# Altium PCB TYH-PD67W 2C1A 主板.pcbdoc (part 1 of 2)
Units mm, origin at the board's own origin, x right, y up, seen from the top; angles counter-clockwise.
Board outline 94.32 x 66.89 mm, 5 copper layers (Top Layer, Signal Layer 3, Signal Layer 1, Signal Layer 2, Bottom Layer), stack 0.941 mm thick; 52 components, 153 nets, 152 pads, 297 vias.
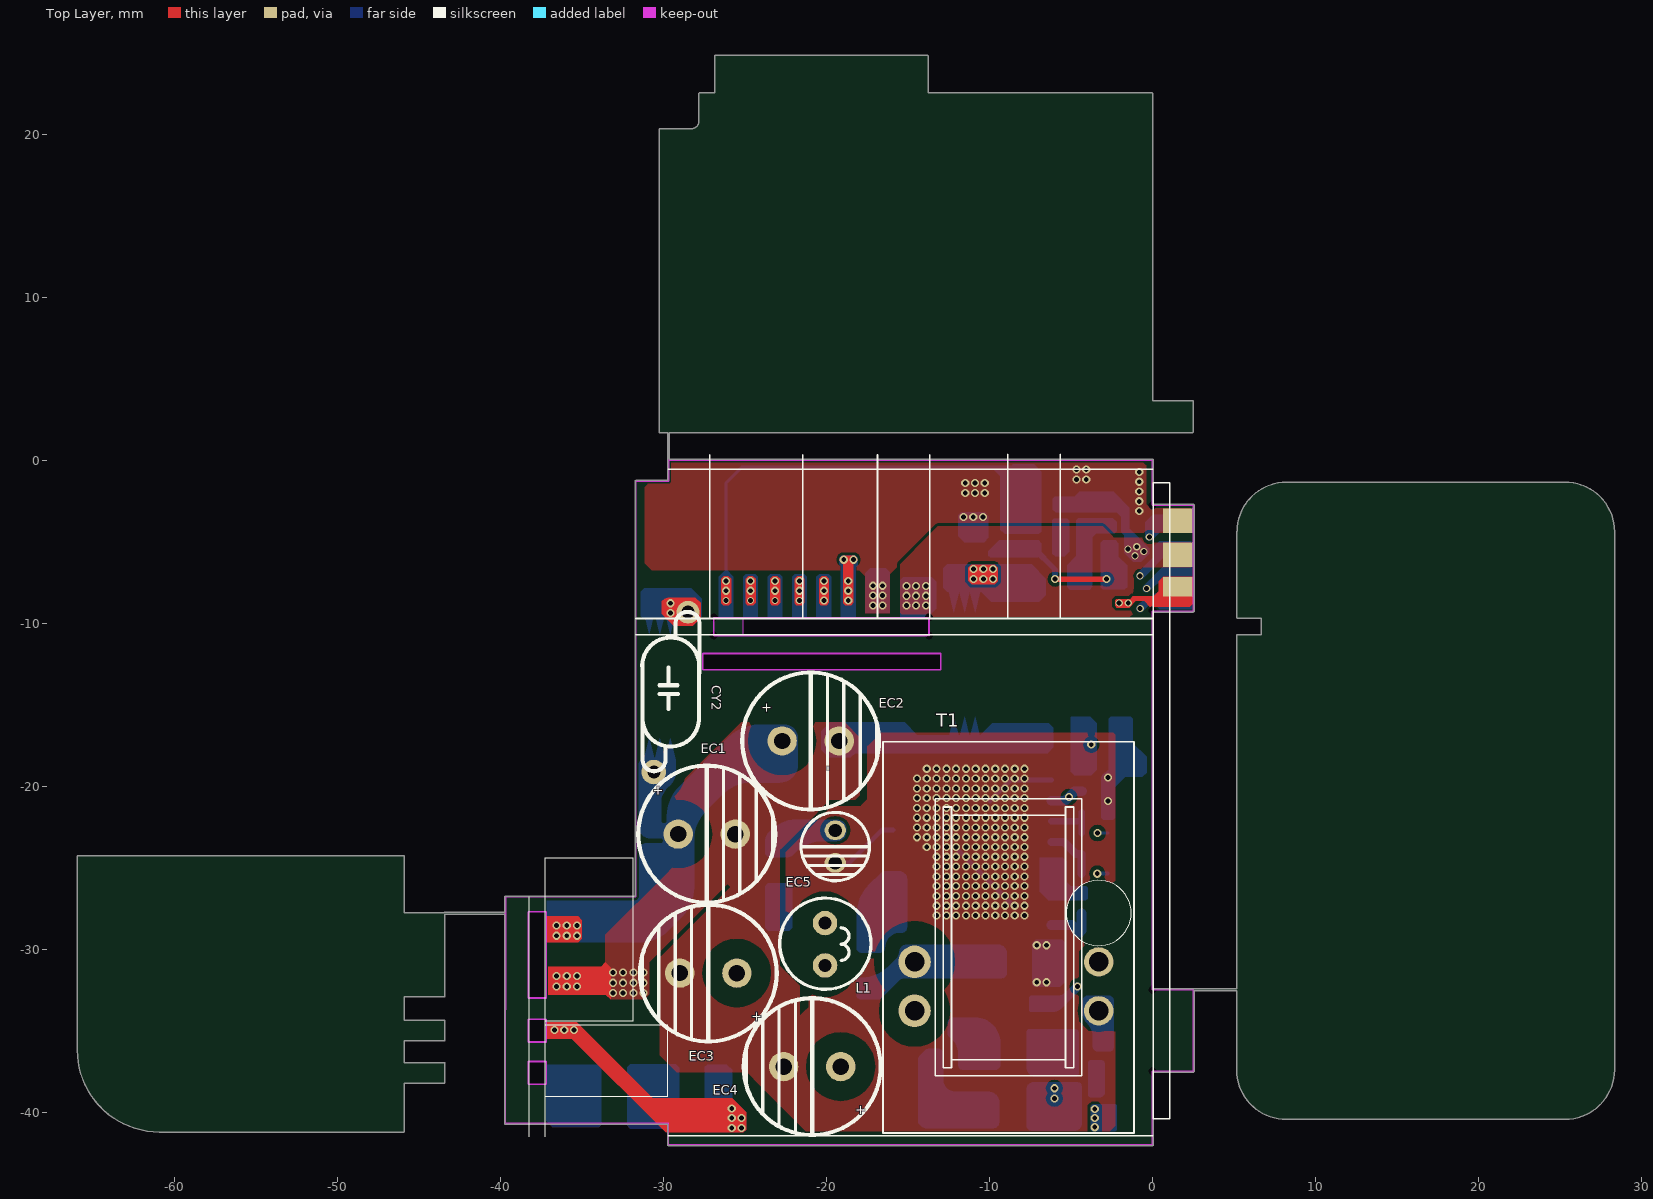
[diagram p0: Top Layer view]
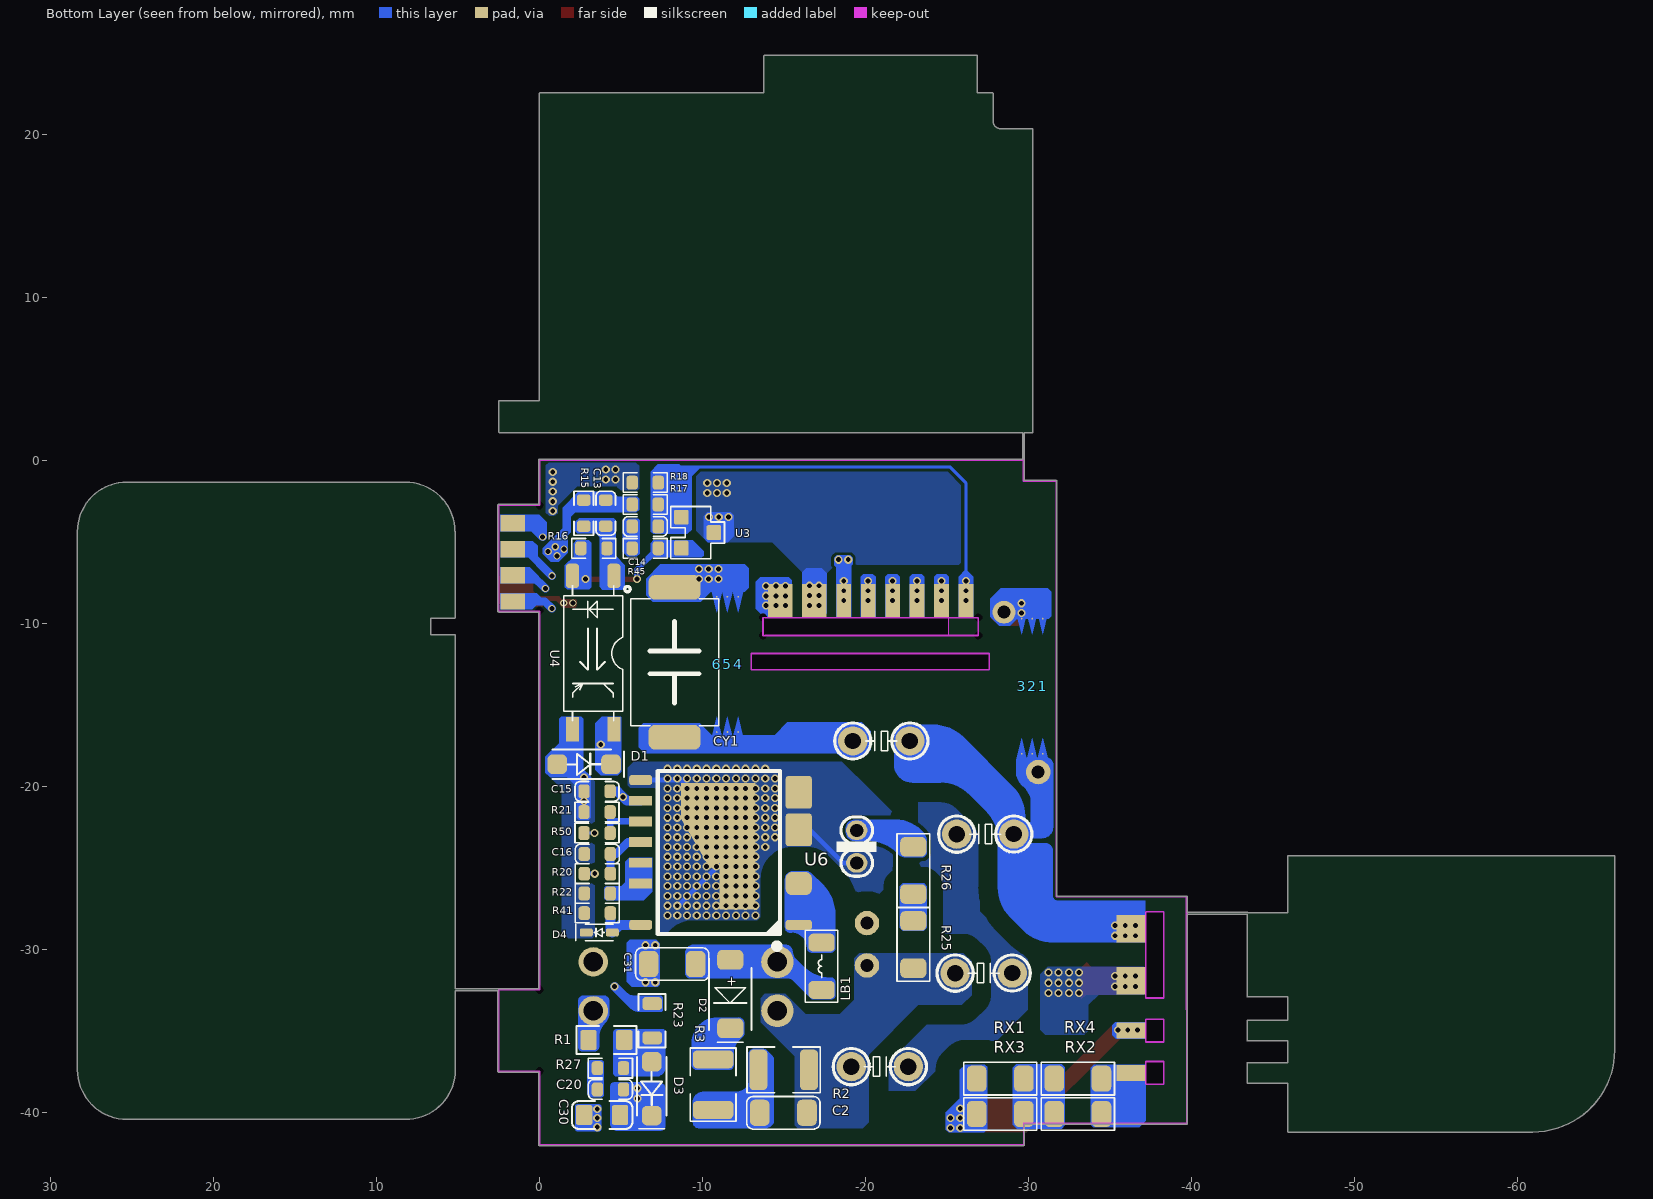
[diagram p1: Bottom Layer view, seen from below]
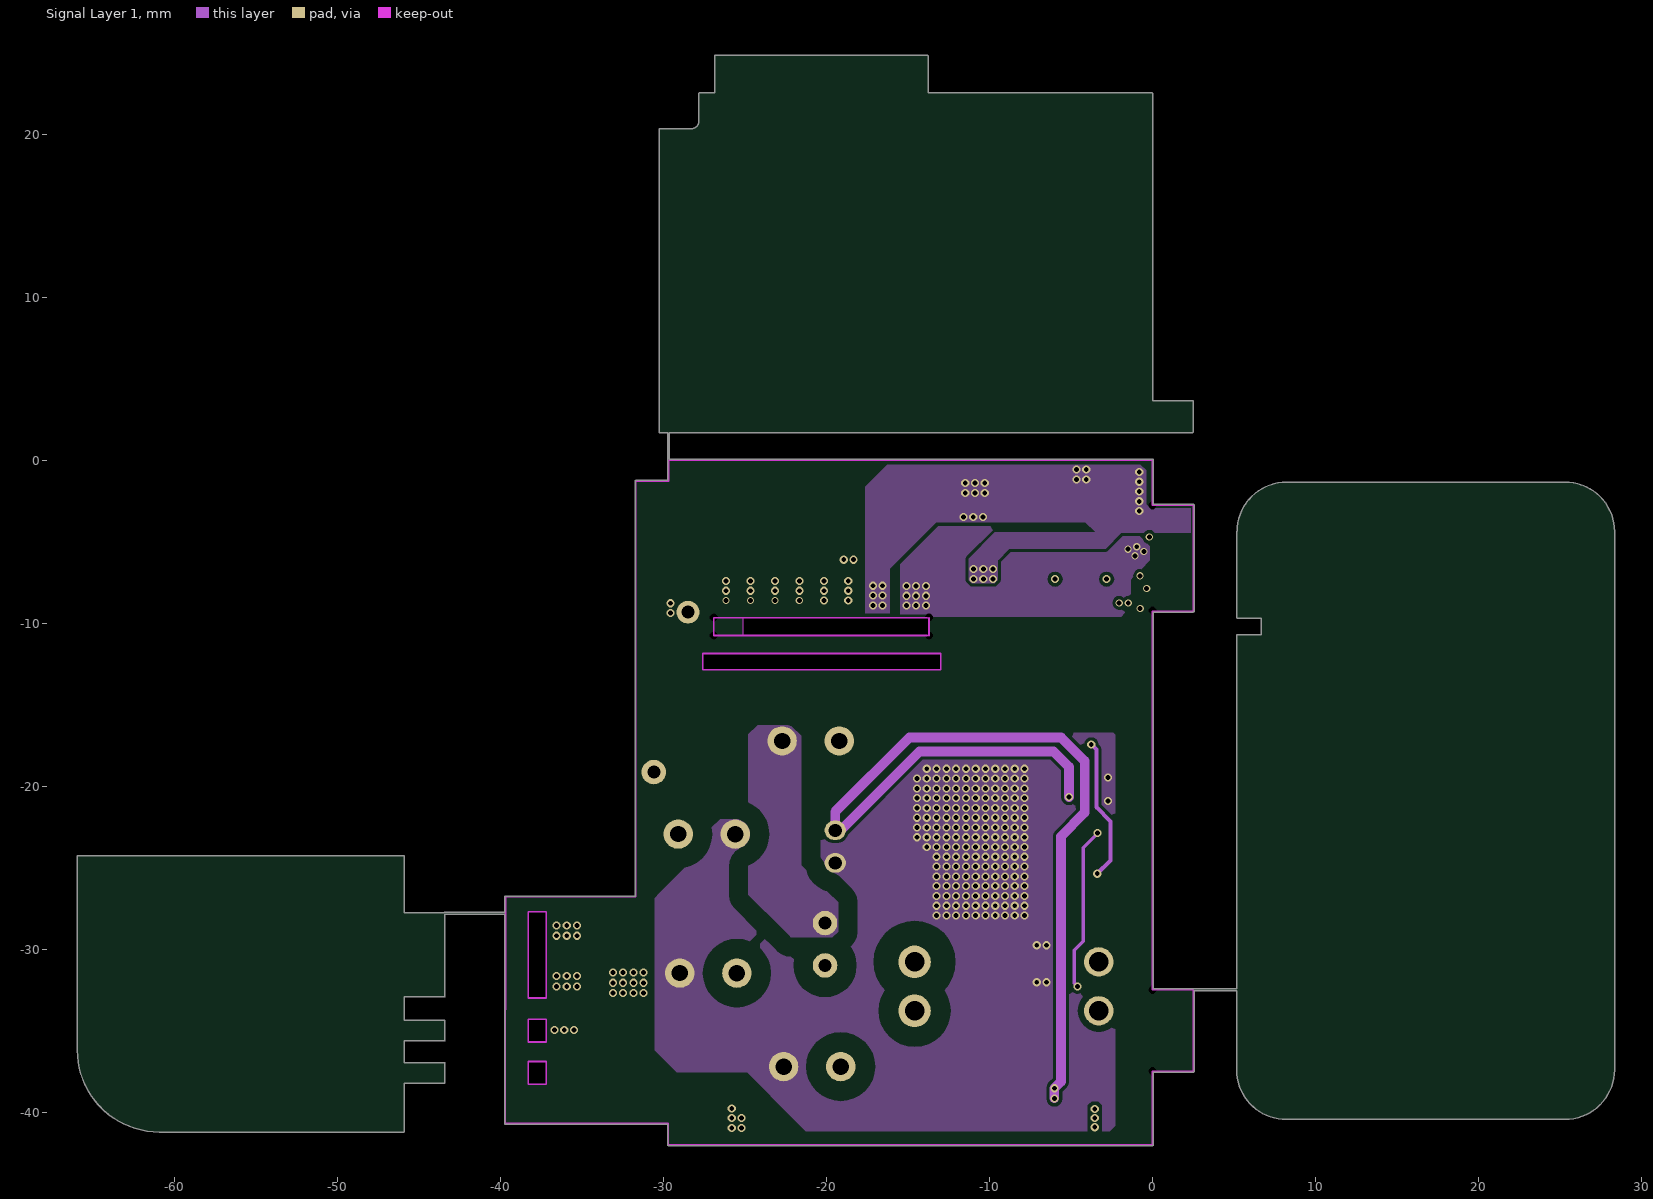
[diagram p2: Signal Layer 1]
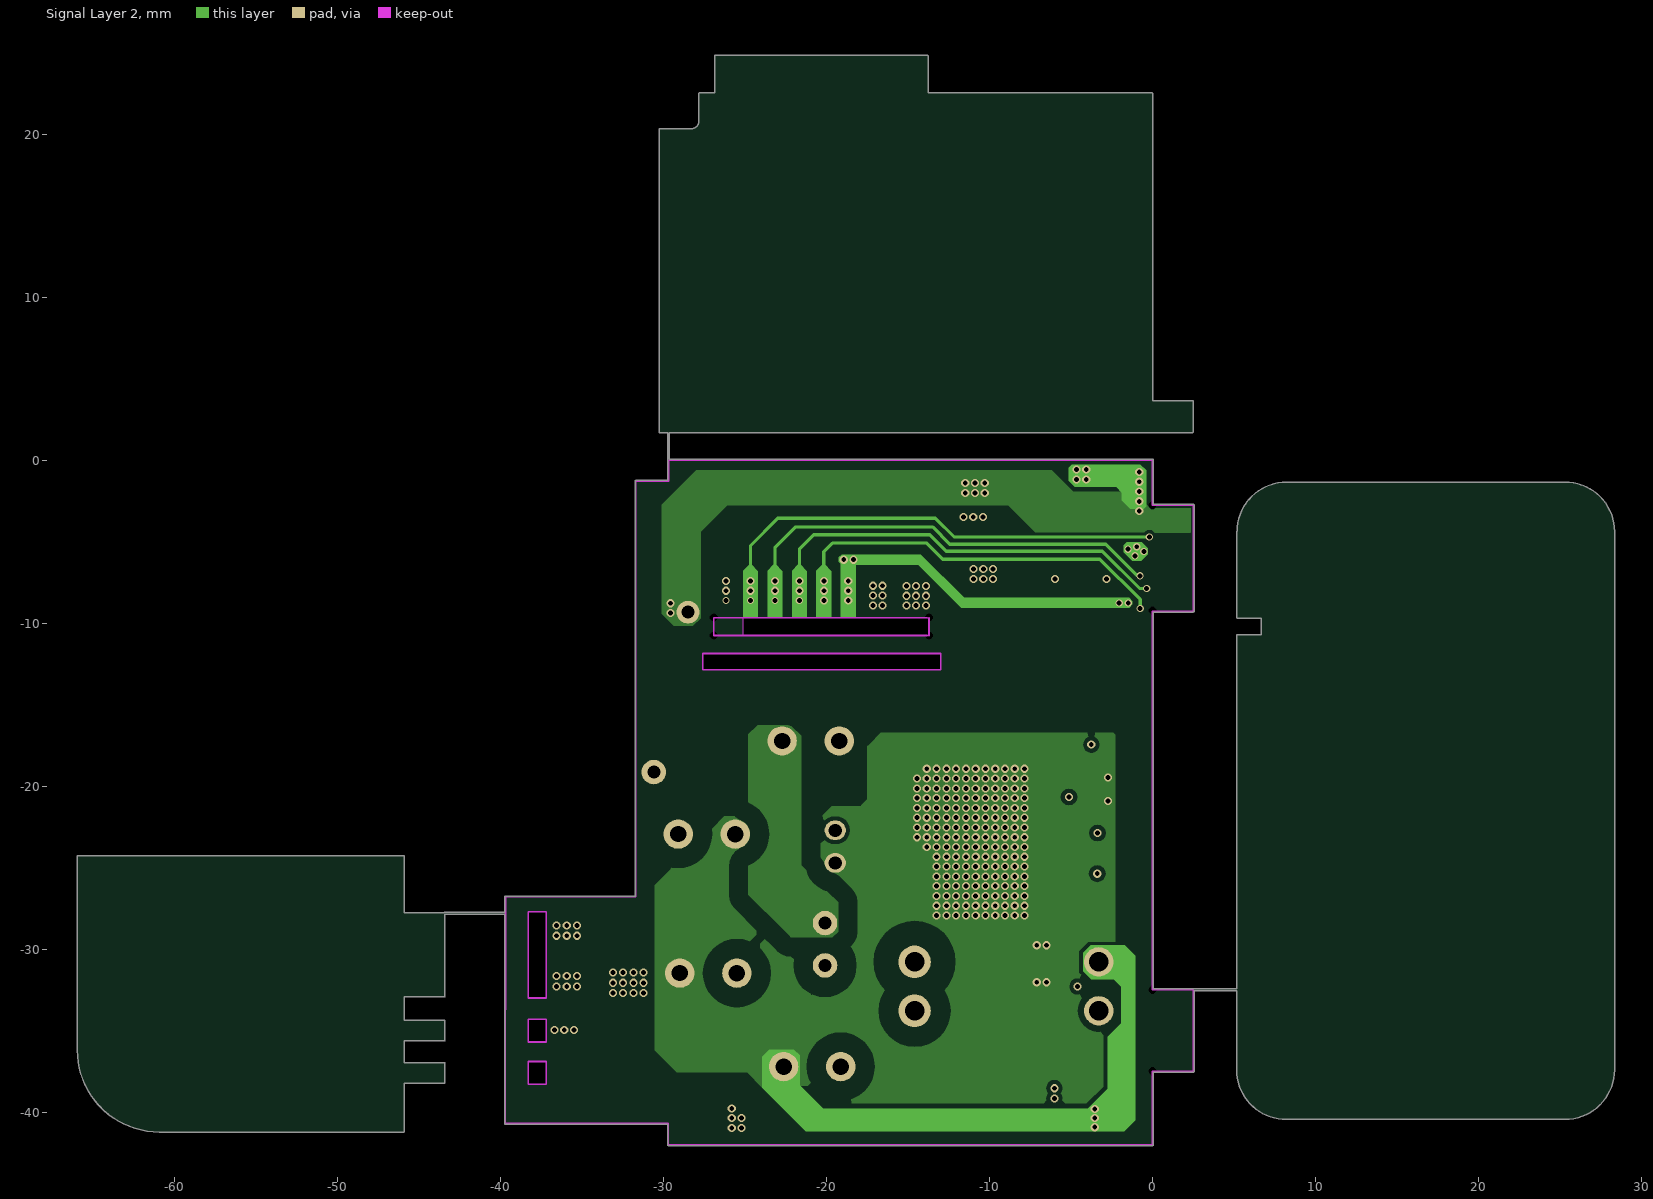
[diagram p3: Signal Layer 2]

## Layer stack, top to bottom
Top Solder: solder mask 0.0102, Solder Resist, Dk 3.5
Top Layer: signal copper 0.0356
Dielectric 1: core 0.254, FR-4, Dk 4.2
Signal Layer 3: signal copper 0.036
Dielectric 4: prepreg 0.127, Dk 4.2
Signal Layer 1: signal copper 0.036
Dielectric 2: core 0.254, Dk 4.2
Signal Layer 2: signal copper 0.036
Dielectric 3: prepreg 0.127, Dk 4.2
Bottom Layer: signal copper 0.0356
Bottom Solder: solder mask 0.0102, Solder Resist, Dk 3.5

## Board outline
-60.945,-41.225 -45.944,-41.225 ccw(c-45.944,-41.2) -45.919,-41.2 -45.919,-38.225 -43.445,-38.225 ccw(c-43.445,-38.2) -43.419,-38.2 -43.419,-37 ccw(c-43.445,-37) -43.445,-36.975 -45.919,-36.975 -45.919,-35.625 -43.445,-35.625 ccw(c-43.445,-35.6) -43.419,-35.6 -43.419,-34.4 ccw(c-43.445,-34.4) -43.445,-34.375 -45.919,-34.375 -45.919,-32.925 -43.445,-32.925 ccw(c-43.445,-32.9) -43.419,-32.9 -43.419,-27.85 -39.751,-27.85 -39.759,-40.693 ccw(c-39.709,-40.7) -39.709,-40.75 -29.759,-40.752 -29.76,-42.002 ccw(c-29.71,-42.002) -29.71,-42.052 0,-42.052 ccw(c0,-42.002) 0.05,-42.002 0.05,-37.55 2.5,-37.55 ccw(c2.5,-37.5) 2.55,-37.5 2.55,-32.55 5.163,-32.55 5.16,-37.409 ccw(c5.21,-37.409) 5.16,-37.409 ccw(c8.207,-37.409) 8.207,-40.456 ccw(c8.207,-40.406) 8.207,-40.456 ccw(c8.207,-40.406) 8.207,-40.456 25.296,-40.456 ccw(c25.296,-40.406) 25.308,-40.455 ccw(c25.296,-37.407) 28.344,-37.407 28.352,-4.393 ccw(c28.302,-4.393) 28.352,-4.393 ccw(c28.302,-4.393) 28.351,-4.381 ccw(c25.304,-4.393) 25.304,-1.346 8.229,-1.346 ccw(c8.229,-4.393) 5.181,-4.375 ccw(c5.228,-4.393) 5.178,-4.393 5.175,-9.653 ccw(c5.225,-9.653) 5.225,-9.703 6.674,-9.704 6.673,-10.703 5.225,-10.702 ccw(c5.225,-10.753) 5.174,-10.753 5.163,-32.45 0.05,-32.45 0.05,-9.32 2.5,-9.32 ccw(c2.5,-9.269) 2.55,-9.269 2.55,-2.769 ccw(c2.5,-2.769) 2.5,-2.719 0.05,-2.719 0.05,0 ccw(c0,0) 0,0.05 -29.65,0.05 -29.65,1.682 2.433,1.682 ccw(c2.433,1.733) 2.483,1.733 ccw(c2.433,1.733) 2.482,1.745 ccw(c2.45,1.784) 2.5,1.784 2.5,3.584 ccw(c2.45,3.584) 2.45,3.635 0,3.635 0,22.484 ccw(c-0.05,22.484) -0.014,22.52 ccw(c-0.05,22.484) -0.05,22.535 -13.768,22.535 -13.768,24.784 ccw(c-13.819,24.784) -13.819,24.835 -26.819,24.835 ccw(c-26.819,24.784) -26.869,24.784 -26.869,22.535 -27.789,22.535 ccw(c-27.789,22.484) -27.84,22.483 -27.84,20.784 cw(c-28.289,20.784) -28.289,20.335 cw(c-28.289,20.784) -28.289,20.335 cw(c-28.289,20.284) -28.289,20.335 -30.217,20.335 ccw(c-30.217,20.284) -30.268,20.284 -30.268,1.733 ccw(c-30.217,1.733) -30.217,1.682 -29.75,1.682 -29.75,-1.25 -31.7,-1.25 ccw(c-31.7,-1.3) -31.75,-1.3 -31.75,-26.75 -39.7,-26.75 ccw(c-39.7,-26.8) -39.75,-26.8 -39.751,-27.75 -43.445,-27.75 ccw(c-43.445,-27.8) -43.488,-27.775 -45.919,-27.775 -45.919,-24.3 ccw(c-45.945,-24.3) -45.945,-24.275 -65.945,-24.275 ccw(c-65.945,-24.3) -65.97,-24.3 -65.97,-36.2 ccw(c-60.945,-36.2)
cut-out: -25.119,-9.664 -13.719,-9.664 -13.719,-10.764 -25.119,-10.764
cut-out: -13,-11.862 -27.6,-11.862 -27.6,-12.862 -13,-12.862
cut-out: -38.3,-27.7 -37.2,-27.7 -37.2,-33 -38.3,-33
cut-out: -38.3,-34.3 -37.2,-34.3 -37.2,-35.7 -38.3,-35.7
cut-out: -38.3,-36.9 -37.2,-36.9 -37.2,-38.3 -38.3,-38.3

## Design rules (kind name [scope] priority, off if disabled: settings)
Clearance Clearance_19 [InNet('NetC4_2') vs InNet('PGND')] p1: gap=0.4
Clearance Clearance_18 [InNet('NetR15_1') vs InNet('PGND')] p2: gap=1
Clearance Clearance_17 [InNet('NetN_1') vs InNet('NetBD1_1')] p3: gap=1.55
Clearance Clearance_16 [InNet('NetN_1') vs InNet('PGND')] p4: gap=1.5
Clearance Clearance_15 [InNet('VIN') vs InNet('PGND')] p5 off: gap=5.8
Clearance Clearance_14 [InNet('CS') vs InNet('Bais-L')] p6: gap=0.45
Clearance Clearance_13 [InNet('SW') vs InNet('CS')] p7: gap=1.5
Clearance Clearance_12 [InNet('NetR15_1') vs InNet('CS')] p8: gap=1
Clearance Clearance_11 [InNet('NetBD1_3') vs InNet('CS')] p9: gap=1.1
Clearance Clearance_10 [InNet('HV') vs InNet('CS')] p10: gap=1.1
Clearance Clearance_9 [InNet('NetL2_1') vs InNet('CS')] p11: gap=1.5
Clearance Clearance_8 [InNet('NetC1_2') vs InNet('PGND')] p12: gap=1.2
Clearance Clearance_7 [InNet('NetBD1_3') vs InNet('PGND')] p13: gap=1.2
Clearance Clearance_6 [InNet('NetC2_2') vs InNet('PGND')] p14: gap=1.3
Clearance Clearance_5 [InNet('Bais-L') vs InNet('PGND')] p15: gap=0.45
Clearance Clearance_4 [InNet('SW') vs InNet('PGND')] p16: gap=1.5
Clearance Clearance_3 [InNet('HV') vs InNet('PGND')] p17: gap=1.2
Clearance Clearance_2 [InNet('NetL2_1') vs InNet('PGND')] p18: gap=1.5
Clearance Clearance_1 [OnLayer('Keep-Out Layer')] p19: gap=0.1
Clearance [All] p20: gap=0.2
PlaneConnect [All] p1: planeconnectstyle=Direct reliefexpansion=0.508 reliefentries=4 reliefconductorwidth=0.3 reliefairgap=0.254
PolygonConnect [All] p1: connectstyle=Direct reliefconductorwidth=0.3 reliefentries=4 polygonreliefangle="90 Angle" airgapwidth=0.3
RoutingVias [All] p1: holewidth=0.711 width=1.27 viastyle="Through Hole" minholewidth=0.711 minwidth=1.27 maxholewidth=0.711 maxwidth=1.27
SolderMaskExpansion [All] p1: expansion=0.05
Width [All] p1: maxlimit=10 minlimit=0.1 preferedwidth=0.2
28 further rules are at their usual default settings.

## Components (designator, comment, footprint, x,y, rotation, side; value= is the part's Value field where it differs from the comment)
1 "Comment" PET -30.881,-18.022 r180 top
2 "Comment" PET -30.231,-18.022 r180 top
3 "Comment" PET -29.581,-18.022 r180 top
4 "Comment" PET -12.187,-16.685 r180 top
5 "Comment" PET -11.537,-16.685 r180 top
6 "Comment" PET -10.887,-16.685 r180 top
C2 "1nF/1KV/1206" 1206CA -16.415,-40.045 r0 bottom (schematic designator C1)
C13 "33nF/25V/0402" 0603CX#1 -4.07,-3.254 r90 bottom (schematic designator C21)
C14 "0.1uF" 0603CX#2 -7.289,-4.068 r0 bottom
C15 "2.2uF/25V/0603" 0603CX#2 -4.335,-20.321 r0 bottom (schematic designator C7)
C16 "470pF/25V/0402" 0603CX#1 -3.554,-24.167 r0 bottom (schematic designator C5)
C20 "220PF/250V/0805" 0603CX#2 -3.556,-38.612 r180 bottom (schematic designator C4)
C30 "1nF/1KV/1206" 0805C -5.697,-41.031 r0 bottom (schematic designator C1)
C31 "47PF/1KV/1206" 1206CA -9.595,-30.922 r0 bottom (schematic designator C2)
CY1 "470pF/400V" Y1-SMT -8.294,-12.405 r270 bottom (schematic designator CY2)
CY2 "470pF/400V" Y1-N -30.601,-19.138 r270 top
D1 "ER07J/SOD-123" SOD-123A -4.392,-18.66 r0 bottom (schematic designator D3)
D2 "S2M" SMAF -11.707,-32.762 r270 bottom (schematic designator D1)
D3 "ER07J/SOD-123" SOD-123A -6.889,-40.217 r90 bottom
D4 "ER07J/SOD-123" SOD-523 -4.474,-28.986 r0 bottom (schematic designator D3)
EC1 "33uF/400V/10*20max" EC-8*18L -27.354,-22.945 r90 top (schematic designator EC3)
EC2 "33uF/400V/10*20max" EC-8*18L -20.975,-17.23 r90 top (schematic designator EC1)
EC3 "33uF/400V/10*20max" EC-8*18L -27.256,-31.475 r270 top
EC4 "33uF/400V/10*20max" EC-8*18L -20.881,-37.213 r270 top (schematic designator EC3)
EC5 "4.7uF/100V/5*11" EC-4*7L -19.468,-22.712 r0 top (schematic designator C6)
L1 "LGB0510  80uH" L-5*11 -20.095,-28.604 r270 top
LB1 "600R@100MHZ" 1206L -17.313,-29.602 r270 bottom (schematic designator L2)
R1 "2.2R/0805" 0805R -2.946,-35.577 r180 bottom (schematic designator R13)
R2 "300K/1206" 1210RS -16.535,-37.408 r0 bottom (schematic designator R1)
R3 "10R/0805" 1210RS -10.657,-39.87 r90 bottom (schematic designator R4)
R15 "1K/0402" 0603RX#1 -2.719,-3.254 r270 bottom (schematic designator R22)
R16 "1M/0402" 0603RX#1 -3.343,-5.412 r0 bottom (schematic designator R21)
R17 "100K" 0603RX#1 -6.49,-2.723 r180 bottom
R18 "95.3K" 0603RX#1 -6.49,-1.379 r180 bottom
R20 "51R/0402" 0603RX#1 -3.554,-25.374 r0 bottom (schematic designator R9)
R21 "18K/0402" 0603RX#1 -3.535,-21.596 r0 bottom (schematic designator R14)
R22 "220K/0805" 0603RX#2 -2.754,-26.588 r180 bottom (schematic designator R7)
R23 "220K/0805" 0805RX -6.915,-33.348 r270 bottom (schematic designator R7)
R25 "10K/1206" 1206RA -21.936,-31.92 r90 bottom (schematic designator R15)
R26 "10K/1206" 1206RA -21.936,-27.374 r90 bottom (schematic designator R15)
R27 "10R/0805" 0603RX#2 -5.156,-37.307 r0 bottom (schematic designator R10)
R41 "51R/0402" 0603RX#1 -3.554,-27.796 r180 bottom (schematic designator R9)
R45 "95.3K" 0603RX#1 -6.49,-5.412 r180 bottom
R50 "18K/0402" 0603RX#1 -3.535,-22.885 r0 bottom (schematic designator R14)
RX1 "2M 1206" 1206RA -30.473,-38.952 r0 bottom
RX2 "2M 1206" 1206RA -35.234,-41.117 r0 bottom
RX3 "2M 1206" 1206RA -30.473,-41.117 r0 bottom
RX4 "2M 1206" 1206RA -35.234,-38.952 r0 bottom
T1 "Comment" "ATQ2315P 4+4" -14.603,-24.788 r0 top
U3 "2N7002KL SOT-23" SOT-23_R -9.704,-4.446 r270 bottom (schematic designator Q8)
U4 "LTV-217-B" CT1018 -4.971,-6.357 r270 bottom
U6 "Comment" MK2789IAM/ESOP10(分) -14.76,-19.074 r180 bottom

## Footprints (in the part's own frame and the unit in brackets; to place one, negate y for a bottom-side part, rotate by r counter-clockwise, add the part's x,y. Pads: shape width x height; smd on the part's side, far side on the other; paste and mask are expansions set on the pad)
0603CX#1 [mm]
  rrect50% 0.7x0.85 smd: 1(-0.8,0) 2(0.8,0)
  silkscreen extent -1.35,-0.6 1.35,0.6, body extent -0.8,-0.41 0.8,0.41, height 0.81
0603CX#2 [mm]
  rrect50% 0.7x0.85 smd: 1(0,0) 2(1.6,0)
  silkscreen extent -0.55,-0.6 2.15,0.6, body extent 0,-0.41 1.6,0.41, height 0.81
0603RX#1 [mm]
  rrect50% 0.7x0.85 smd: 1(-0.8,0) 2(0.8,0)
  silkscreen extent -1.35,-0.6 1.35,0.6, body extent -0.77,-0.42 0.78,0.43, height 0.45
0603RX#2 [mm]
  rrect50% 0.7x0.85 smd: 1(0,0) 2(1.6,0)
  silkscreen extent -0.55,-0.6 2.15,0.6, body extent 0.03,-0.42 1.58,0.43, height 0.45
0805C [mm]
  rrect20% 1x1.2 smd: 1(0.75,-0.85) 2(2.95,-0.85)
  silkscreen extent 0,-1.7 3.7,0, body extent 0.85,-1.46 2.85,-0.24, height 0.51
0805R [mm]
  rrect20% 1x1.2 smd: 1(0.066,-0.001) 2(2.266,-0.001)
  silkscreen extent -0.68,-0.85 3.02,0.85, body extent 0.17,-0.63 2.17,0.62, height 0.45
0805RX [mm]
  rrect50% 0.8x1.2 smd: 1(0,0) 2(2.1,0)
  silkscreen extent -0.6,-0.83 2.7,0.83, body extent 0.05,-0.61 2.05,0.61, height 0.51
1206CA [mm]
  rrect50% 1.2x1.6 smd mask+0.03: 1(0,0) 2(2.9,0)
  silkscreen extent -0.8,-1 3.7,1, body extent -0.15,-0.81 3.05,0.81, height 1.21
1206L [mm]
  rrect50% 1.1x1.6 smd mask+0.03: 1(0,0) 2(2.9,0)
  silkscreen extent -0.75,-1 3.65,1, body extent -0.15,-0.8 3.05,0.8, height 1
1206RA [mm]
  rrect50% 1.2x1.6 smd mask+0.03: 1(3.65,-1) 2(0.75,-1)
  silkscreen extent -0.05,-2 4.45,0, body extent 0.6,-1.8 3.8,-0.2, height 0.55
1210RS [mm]
  rrect50% 1.1x2.5 smd mask+0.03: 1(3.1,0) 2(0,0)
  silkscreen extent -0.7,-1.4 3.8,1.4, body extent -0.05,-1.25 3.15,1.25, height 0.55
"ATQ2315P 4+4" [mm]
  round 2 on Top Overlay mask+0.04: 1(0,0) 2(0,-3) 7(11.3,-3) 8(11.3,0)
  round 2 hole 1.2 mask+0.04: 3(0,-6) 4(0,-9)
  round 1.8 hole 1.2 mask+0.04: 5(11.3,-9) 6(11.3,-6)
  silkscreen extent -1.94,-16.5 13.46,7.5, body extent -1.79,-16.02 13.31,7.08, height 19.06
CT1018 [mm]
  rrect50% 1.5x0.8 smd: 1(0.75,-0.4) 2(0.75,-2.94)
  rect 1.5x0.8 smd: 3(10.15,-2.941) 4(10.15,-0.4)
  silkscreen extent 1.36,-3.47 9.64,0.59, body extent 0.38,-3.47 10.58,0.13, height 2.3
EC-4*7L [mm]
  oval 1.3x1.2 hole 0.8: 1(0,0) 2(0,-2)
  silkscreen extent -2.1,-3.1 2.1,1.1, body extent -2.01,-3.04 1.99,0.98, height 8.04
EC-8*18L [mm]
  round 1.8 hole 1: 1(0,1.749) 2(-0.002,-1.751)
  silkscreen extent -4.2,-4.2 4.2,4.2, body extent -4,-4 4,4, height 18
L-5*11 [mm]
  round 1.5 hole 0.8: 1(-0.2,0) 2(2.4,0)
  silkscreen extent -1.73,-2.77 3.87,2.82, body extent -1.56,-2.61 3.71,2.64, height 11.5
MK2789IAM/ESOP10(分) [mm]
  rrect50% 1.6x0.6 smd: 1(1.15,-9.445)
  rrect50% 1.6x1.4 smd: 2(1.15,-6.905)
  rrect20% 1.6x2 smd: 3(1.15,-3.615) 4(1.15,-1.315)
  rrect50% 1.4x0.6 smd: 5(-8.55,-0.555) 11(-8.55,-9.445)
  rect 1.4x0.6 smd: 7(-8.55,-3.095) 8(-8.55,-4.365) 9(-8.55,-5.635) 10(-8.55,-6.905) EM(-8.55,-1.825)
  rect 2.6x2.165 smd: 12(-4.775,-1.833)
  rect 3.55x2.6 smd rot 120: 12(-4.062,-3.802)
  rect 2.2x7.755 smd: 12(-2.6,-4.627)
  silkscreen extent -7.5,-10.89 0.05,0, body extent -8.91,-10 1.41,0, height 1.85
PET [mm]
  round 0.1 smd far side: 1(0,0) 2(0,-8.3)
  Bottom Layer region: 0.325,0.35 -0.325,0.35 0,-0.95
  Bottom Layer region: 0.35,-8.75 -0.35,-8.75 0,-7.35
SMAF [mm]
  rrect50% 1.2x1.6 smd: 1(-2.1,0) 2(2.1,0)
  silkscreen extent -2.2,-1.3 2.95,1.3, body extent -2.35,-1.25 2.35,1.25, height 1
SOD-123A [mm]
  rrect50% 1.2x1.2 smd: 1(3.3,0) 2(0,0)
  silkscreen extent -0.8,-0.9 3.6,0.9, body extent -0.19,-0.8 3.51,0.8, height 1.22
SOD-523 [mm]
  rrect50% 0.8x0.5 smd: 1(0,0) 2(1.6,0)
  silkscreen extent -0.05,-0.5 2.24,0.5, body extent 0,-0.4 1.6,0.4, height 0.65
SOT-23_R [mm]
  rrect20% 0.9x0.9 smd: 1(-0.95,-1) 2(0.95,-1) 3(0,1)
  silkscreen extent -1.6,-1.65 1.6,1.65, body extent -1.46,-1.44 1.44,1.36, height 1.2
Y1-N [mm]
  round 1.5 hole 0.8: 1(0,0)
  round 1.4 hole 0.8: 2(-9.806,2.096)
  silkscreen extent -9.83,-0.7 -0.05,2.8, body extent -10.14,-1.57 0.34,3.66, height 8.2
Y1-SMT [mm]
  rrect50% 1.5x3.2 smd: 1(-4.6,0) 2(4.6,0)
  silkscreen extent -3.9,-2.7 3.9,2.7, body extent -5,-2.7 5,2.7, height 2.5

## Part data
C2 C15 C16 C20 C30 C31: library part CAP
C13: library part Cap, "Capacitor"
CY1 CY2: library part Cap
D1 D3 D4: library part DIODE
D2: library part Diode_fast, "High Conductance Fast Diode"
EC1 EC2 EC3 EC4 EC5: library part CAPACITOR, "C?"
L1: library part L-1
LB1 R1 R2 R3 R15 R16 R20 R21 R22 R23 R25 R26 R27 R41 R50 RX1 RX2 RX3 RX4: library part Res1, "Resistor"
U3: library part NMOS
U4: library part PC817, "Optocoupler，PC817X2YIPW，4pin SOP"

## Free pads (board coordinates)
  rect 1.8x1 smd far side: 0(-36.3,-37.6)
  rrect20% 1.8x1 smd far side: 0(-36.3,-35)
  rect 1.8x1.7 smd far side: 0(-36.3,-31.95) 0(-36.3,-28.75)
  rect 1.5x2 smd far side: 0(-16.869,-8.614) 1(-14.769,-8.614)
  round 0.2 hole 0.5: 0(0,-9.235) 1(0,-2.769) 2(0,-32.5) 3(0,-37.5) 4(-26.919,-9.664) 5(-13.719,-9.664) 6(-13.719,-10.764) 7(-26.919,-10.764)
  rect 0.9x2 smd far side: 2(-26.169,-8.614) 2(-24.669,-8.614) 2(-23.169,-8.614) 2(-21.669,-8.614) 2(-20.169,-8.614) 2(-18.669,-8.614)
  rect 1.8x1.2 smd: 3(1.55,-7.769)
  rect 1.8x1.5 smd: 3(1.55,-5.819) 3(1.55,-3.719)
  rect 1.5x1 smd far side: 3(1.65,-8.669) 3(1.65,-7.069) 3(1.65,-5.469) 3(1.65,-3.869)

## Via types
v1: diameter 0.5, hole 0.3, Top Layer to Bottom Layer, tented both sides, 283 vias
v2: diameter 0.45, hole 0.3, Top Layer to Bottom Layer, tented both sides, 14 vias

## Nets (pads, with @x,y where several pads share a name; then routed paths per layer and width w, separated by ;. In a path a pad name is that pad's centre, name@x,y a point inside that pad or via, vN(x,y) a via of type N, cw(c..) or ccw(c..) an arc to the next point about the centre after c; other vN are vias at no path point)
3.3V: 
A: C14.2 R45.1
A+: 
A-: 
Bais-L: D3.1 R1.2 R23.2 R27.1
BOOT0: 
CC1: 
CC2: 
CPA: 
CS: 
D: 
D+: 
D-: 
DM: 
DP: 
EM: D4.1 R41.2 U6.11 | length 3.2
  Bottom Layer w0.6: U6.11@-6.21,-28.519 -4.941,-28.519 D4.1@-4.474,-28.986 -4.354,-28.866 R41.2@-4.354,-27.796
EN: 
EN_IC: 
FB: C16.1 R20.1 U6.8 | length 3.4
  Bottom Layer w0.5: U6.8@-6.21,-23.439 -5.431,-23.439 -4.703,-24.167 C16.1@-4.354,-24.167 R20.1@-4.354,-25.374
G-SR: 
GND-C: 
HV: C2.1 EC3.1 EC4.1 L1.2 R2.2 R25.2 T1.4
ISET: R22.2 U6.9 U6.10 | length 3.4
  Bottom Layer w0.5: U6.9@-6.21,-24.709 U6.10@-6.21,-25.979 -5.601,-26.588 R22.2@-4.354,-26.588
KEY: 
KEY1: 
LEDA: 
M: R23.1 R50.2 | length 13.4
  Signal Layer 1 w0.2: v1(-4.611,-32.3) -4.802,-32.11 -4.802,-30.063 -4.258,-29.519 -4.258,-23.77 v1(-3.373,-22.885)
  Bottom Layer w0.2: R23.1@-6.915,-33.348 -5.659,-33.348 v1(-4.611,-32.3) ; v1@-3.359,-22.885 R50.2@-2.735,-22.885
N: 
NetBD1_1: pad.0@-36.3,-35 RX1.1 RX3.1
  other v1: -25.816,-40.973 -25.216,-40.973 -25.816,-40.373 -25.216,-40.373 -25.816,-39.773 -36.698,-34.973 -36.098,-34.973 -35.498,-34.973
NetBD1_3: 1.1 2.1 3.1 CY2.1 EC1.1 EC2.1 L1.1 pad.0@-36.3,-28.75 | length 20.4
  Bottom Layer w0.2: pad.0@-36.3,-28.75 -33.007,-28.75 ccw(c-33.007,-26.21) -31.211,-28.006 -29.847,-26.642 ccw(c-31.643,-24.846) -29.103,-24.846 EC1.1@-29.103,-22.945 -29.103,-22.738 cw(c-26.563,-22.738) -28.359,-20.942 -25.391,-17.973 cw(c-23.595,-19.769) -23.595,-17.229 EC2.1@-22.724,-17.229
  other v1: -36.57,-29.186 -35.942,-29.186 -35.314,-29.186 -36.57,-28.558 -35.942,-28.558 -35.314,-28.558
NetBD2_1: 
NetC1_2: C2.2 R2.1 R3.2
NetC2_2: D2.2 R3.1
NetC3_2: 
NetC4_1: C20.1 R27.2
NetC4_2: R1.1 T1.5
NetC6_1: C15.1 C20.2 C30.1 D3.2 EC5.1 R26.1 U6.EM | length 65.3
  Signal Layer 1 w0.6: v1(-6.025,-39.158) v1(-6.025,-38.537) -5.622,-38.134 -5.622,-23.086 -4.165,-21.629 -4.165,-18.458 -5.605,-17.017 -14.917,-17.017 -19.468,-21.569 EC5.1@-19.468,-22.712 -19.138,-22.712 -14.303,-17.877 -6.069,-17.877 -5.129,-18.817 v1(-5.129,-20.666)
  Bottom Layer w0.6: R26.1@-22.936,-23.724 R26.1@-22.663,-23.451 ; R26.1@-22.882,-23.782 -21.812,-22.712 EC5.1@-19.468,-22.712 ; U6.EM@-6.21,-20.899 -5.362,-20.899 v1(-5.129,-20.666) -4.784,-20.321 C15.1@-4.335,-20.321
NetC10_2: 
NetC21_1: C13.1 R15.2 R16.1 U4.1
NetC22_1: 
NetC24_1: 
NetC25_2: 
NetC26_2: 
NetC30_2: 
NetC31_2: 
NetC100_2: 
NetC101_1: 
NetC101_2: 
NetC112_1: 
NetD4_K: D1.2 R20.2 U4.4 | length 11.9
  Signal Layer 1 w0.25: v1(-3.758,-17.456) -3.447,-17.767 -3.447,-21.296 -2.575,-22.169 -2.575,-24.556 v1(-3.393,-25.374)
  Bottom Layer w0.25: D1.2@-4.392,-18.66 D1.2@-4.282,-18.77 ; D1.2@-4.36,-18.848 -4.099,-18.587 -4.099,-16.551 ; v1(-3.393,-25.374) R20.2@-2.754,-25.374
NetF1_1: 
NetF1_2: 
NetKEY1_1: 
NetL2_1: LB1.1 U6.1 U6.2
NetLF1_2: 
NetN_1: pad.0@-36.3,-37.6 RX2.2 RX4.2
NetNTC2_1: 
NetQ1_3: 
NetQ3_4: 
NetR15_1: R25.1 R26.2
NetR25_2: 
NetR29_1: 
NetR31_2: 
NetR32_2: 
NetR41_2: 
NetR42_2: 
NetR134_1: 
NetRX1_2: 
NetRX3_2: RX1.2 RX2.1 RX3.2 RX4.1
NetU1_26: 
NetU1_27: 
NetU1_28: 
NetU1_29: 
NetU1_30: 
NetU1_32: 
NewNet1: 
NewNet2: 
NewNet3: 
NewNet4: 
NewNet5: 
NewNet6: 
NewNet7: 
NewNet8: 
NewNet9: 
NewNet10: 
NewNet11: 
NewNet12: 
NewNet13: 
NewNet14: 
NewNet15: 
NewNet16: 
NewNet18: 
NewNet22: 
NewNet23: 
NewNet24: 
NewNet25: 
NewNet28: 
NewNet32: 
NewNet33: C14.1 pad.2@-26.169,-8.614 R17.2 R18.2 U3.1 | length 30
  Bottom Layer w0.2: v1(-26.169,-7.414) -26.169,-1.402 -25.186,-0.419 -8.25,-0.419 R18.2@-7.29,-1.379 C14.1@-7.29,-4.068 -8.132,-4.068 U3.1@-8.704,-3.496
  other v1: -26.169,-8.014
  other v2: -26.169,-8.614
NewNet34: 
NewNet36: 
NewNet38: 
NewNet40: 
NewNet41: 
NewNet42: 
OPTO: R16.2 R45.2 U3.2 U4.2 | length 5.6
  Top Layer w0.35: v1(-5.982,-7.304) v1(-2.824,-7.304)
  Bottom Layer w0.35: R45.2@-7.29,-5.412 -5.982,-6.72 v1(-5.982,-7.304)
OTP: 
PA2: 
PA4: 
PA5: 
PA6: 
PA7: 
PA8: 
PA9: 
PB0: 
PB1: 
PF0: 
PF1: 
PF3: 
PGND: 4.1 5.1 6.1 C15.2 C16.2 C30.2 C31.2 CY1.2 D1.1 D4.2 EC1.2 EC2.2 EC3.2 EC4.2 EC5.2 pad.0@-36.3,-31.95 R21.2 R22.1 R41.1 T1.6 U4.3 U6.3 U6.4 U6.5 U6.12 | length 32.9
  Signal Layer 2 w0.3: v1(-3.546,-40.928) -2.771,-40.928 -1.451,-39.608 -1.451,-31.626 -2.29,-30.787 T1.6@-3.303,-30.787
  Bottom Layer w0.3: EC5.2@-19.468,-24.712 -18.609,-24.712 -16.585,-22.689 U6.3@-15.91,-22.689 ; U6.12@-12.16,-23.702 v1@-8.642,-27.22 ; U6.12@-9.985,-20.907 -8.707,-19.629 U6.5@-6.21,-19.629 ; R21.2@-2.735,-21.596 v1(-2.735,-19.465) -1.93,-18.66 D1.1@-1.092,-18.66 -1.559,-18.194 -1.559,-16.551
  other v1: -3.546,-40.364 -3.546,-39.81 -33.11,-32.698 -32.483,-32.698 -31.855,-32.698 -31.227,-32.698 -36.57,-32.287 -35.942,-32.287 -35.314,-32.287 -33.11,-32.07 -32.483,-32.07 -31.855,-32.07 -31.227,-32.07 -7.104,-32.039 -6.504,-32.039 -36.57,-31.659 -35.942,-31.659 -35.314,-31.659 -33.11,-31.442 -32.483,-31.442 -31.855,-31.442 -31.227,-31.442 -7.104,-29.766 -6.504,-29.766 -13.252,-27.939 -12.652,-27.939 -12.052,-27.939 -11.452,-27.939 -10.852,-27.939 -10.252,-27.939 -9.652,-27.939 -9.052,-27.939 -8.452,-27.939 -7.852,-27.939 -13.252,-27.339 -12.652,-27.339 -12.052,-27.339 -11.452,-27.339 -10.852,-27.339 -10.252,-27.339 -9.652,-27.339 -9.052,-27.339 -8.452,-27.339 -7.852,-27.339 -13.252,-26.739 -12.652,-26.739 -12.052,-26.739 -11.452,-26.739 -10.852,-26.739 -10.252,-26.739 -9.652,-26.739 -9.052,-26.739 -8.452,-26.739 -7.852,-26.739 -13.252,-26.139 -12.652,-26.139 -12.052,-26.139 -11.452,-26.139 -10.852,-26.139 -10.252,-26.139 -9.652,-26.139 -9.052,-26.139 -8.452,-26.139 -7.852,-26.139 -13.252,-25.539 -12.652,-25.539 -12.052,-25.539 -11.452,-25.539 -10.852,-25.539 -10.252,-25.539 -9.652,-25.539 -9.052,-25.539 -8.452,-25.539 -7.852,-25.539 -13.252,-24.939 -12.652,-24.939 -12.052,-24.939 -11.452,-24.939 -10.852,-24.939 -10.252,-24.939 -9.652,-24.939 -9.052,-24.939 -8.452,-24.939 -7.852,-24.939 -13.252,-24.339 -12.652,-24.339 -12.052,-24.339 -11.452,-24.339 -10.852,-24.339 -10.252,-24.339 -9.652,-24.339 -9.052,-24.339 -8.452,-24.339 -7.852,-24.339 -13.852,-23.739 -13.252,-23.739 -12.652,-23.739 -12.052,-23.739 -11.452,-23.739 -10.852,-23.739 -10.252,-23.739 -9.652,-23.739 -9.052,-23.739 -8.452,-23.739 -7.852,-23.739 -14.452,-23.139 -13.852,-23.139 -13.252,-23.139 -12.652,-23.139 -12.052,-23.139 -11.452,-23.139 -10.852,-23.139 -10.252,-23.139 -9.652,-23.139 -9.052,-23.139 -8.452,-23.139 -7.852,-23.139 -14.452,-22.539 -13.852,-22.539 -13.252,-22.539 -12.652,-22.539 -12.052,-22.539 -11.452,-22.539 -10.852,-22.539 -10.252,-22.539 -9.652,-22.539 -9.052,-22.539 -8.452,-22.539 -7.852,-22.539 -14.452,-21.939 -13.852,-21.939 -13.252,-21.939 -12.652,-21.939 -12.052,-21.939 -11.452,-21.939 -10.852,-21.939 -10.252,-21.939 -9.652,-21.939 -9.052,-21.939 -8.452,-21.939 -7.852,-21.939 -14.452,-21.339 -13.852,-21.339 -13.252,-21.339 -12.652,-21.339 -12.052,-21.339 -11.452,-21.339 -10.852,-21.339 -10.252,-21.339 -9.652,-21.339 -9.052,-21.339 -8.452,-21.339 -7.852,-21.339 -2.741,-20.925 -14.452,-20.739 -13.852,-20.739 -13.252,-20.739 -12.652,-20.739 -12.052,-20.739 -11.452,-20.739 -10.852,-20.739 -10.252,-20.739 -9.652,-20.739 -9.052,-20.739 -8.452,-20.739 -7.852,-20.739 -14.452,-20.139 -13.852,-20.139 -13.252,-20.139 -12.652,-20.139 -12.052,-20.139 -11.452,-20.139 -10.852,-20.139 -10.252,-20.139 -9.652,-20.139 -9.052,-20.139 -8.452,-20.139 -7.852,-20.139 -14.452,-19.539 -13.852,-19.539 -13.252,-19.539 -12.652,-19.539 -12.052,-19.539 -11.452,-19.539 -10.852,-19.539 -10.252,-19.539 -9.652,-19.539 -9.052,-19.539 -8.452,-19.539 -7.852,-19.539 -13.852,-18.939 -13.252,-18.939 -12.652,-18.939 -12.052,-18.939 -11.452,-18.939 -10.852,-18.939 -10.252,-18.939 -9.652,-18.939 -9.052,-18.939 -8.452,-18.939 -7.852,-18.939
RS: 
RST: 
SCL: pad.2@-24.669,-8.614 pad.3@1.65,-3.869 | length 30
  Signal Layer 2 w0.2: v1(-24.669,-7.414) -24.669,-5.243 -22.992,-3.566 -13.321,-3.566 -12.169,-4.718 v2(-0.199,-4.718)
  Bottom Layer w0.5: v2(-0.199,-4.718) 0.65,-3.869 pad.3@1.65,-3.869
  other v1: -24.669,-8.014
  other v2: -24.669,-8.614
SCL1: 
SDA: pad.2@-23.169,-8.614 pad.3@1.65,-5.469 | length 29.3
  Signal Layer 2 w0.2: v1(-23.169,-7.414) -23.169,-5.382 -21.885,-4.098 -13.496,-4.098 -12.436,-5.158 -2.87,-5.158 -0.927,-7.101 v2(-0.768,-7.101)
  Bottom Layer w0.5: v2(-0.768,-7.101) 0.864,-5.469 pad.3@1.65,-5.469
  other v1: -23.169,-8.014
  other v2: -23.169,-8.614
SDA1: 
SET: 
SGND: 1.2 2.2 3.2 4.2 5.2 6.2 CY1.1 CY2.2 pad.0@-16.869,-8.614 pad.1@0,-2.769 pad.3@1.55,-3.719 R18.1 U3.3
  other v1: -29.578,-9.383 -17.161,-8.91 -16.561,-8.91 -29.578,-8.783 -17.161,-8.31 -16.561,-8.31 -17.161,-7.71 -16.561,-7.71 -10.984,-7.286 -10.384,-7.286 -9.784,-7.286 -10.984,-6.686 -10.384,-6.686 -9.784,-6.686 -11.602,-3.5 -11.002,-3.5 -10.402,-3.5 -0.819,-3.128 -0.819,-2.528 -11.495,-2.014 -10.895,-2.014 -10.295,-2.014 -0.819,-1.928 -11.495,-1.414 -10.895,-1.414 -10.295,-1.414 -0.819,-1.328 -4.67,-1.179 -4.07,-1.179 -0.819,-0.728 -4.67,-0.579 -4.07,-0.579
SRCG_A: 
SW: C31.1 D2.1 LB1.2 T1.3
SW-SR: 
SWCLK: pad.2@-21.669,-8.614 pad.3@1.65,-7.069 | length 27.3
  Signal Layer 2 w0.2: v1(-21.669,-7.414) -21.669,-5.46 -20.795,-4.586 -13.678,-4.586 -12.666,-5.598 -3.075,-5.598 -0.796,-7.878 v2(-0.362,-7.878)
  Bottom Layer w0.5: v2(-0.362,-7.878) 0.446,-7.069 pad.3@1.65,-7.069
  other v1: -21.669,-8.014
  other v2: -21.669,-8.614
SWCLK1: 
SWCLK2: 
SWDIO: pad.2@-20.169,-8.614 pad.3@1.65,-8.669 | length 26
  Signal Layer 2 w0.2: v1(-20.169,-7.414) -20.169,-5.614 -19.642,-5.088 -13.862,-5.088 -12.873,-6.077 -3.229,-6.077 -0.76,-8.546 v2(-0.76,-9.104)
  Bottom Layer w0.5: v2(-0.76,-9.104) -0.326,-8.669 pad.3@1.65,-8.669
  other v1: -20.169,-8.614 -20.169,-8.014
SWDIO1: 
SWDIO2: 
SWRST: 
TXD: 
U2-2: 
V3V3: 
VBUS: 
VC: 
VDD: 
VDD1: 
VDS: 
VFB: 
VFB1: 
VIN: C13.2 pad.1@-14.769,-8.614 pad.3@1.55,-5.819 pad.5 R15.1 R17.1
  other v1: -15.105,-8.926 -14.505,-8.926 -13.905,-8.926 -15.105,-8.326 -14.505,-8.326 -13.905,-8.326 -15.105,-7.726 -14.505,-7.726 -13.905,-7.726
  other v2: -1.081,-5.873 -0.533,-5.611 -1.511,-5.46 -0.972,-5.317
VMS: R21.1 R50.1 U6.7 | length 3.7
  Bottom Layer w0.4: U6.7@-6.21,-22.169 -4.335,-22.169 R21.1@-4.335,-21.596 R50.1@-4.335,-22.885
VOUT1: pad.0@0,-9.235 pad.2@-18.669,-8.614 pad.3@1.55,-7.769 | length 18.8
  Top Layer w0.2: pad.3@1.081,-8.238 pad.3@1.55,-7.769 pad.3@1.376,-7.596
  Top Layer w0.5: v1(-18.948,-6.11) v1(-18.348,-6.11)
  Signal Layer 2 w0.2: v1@-18.348,-6.087 -14.319,-6.087 -11.596,-8.81 v2@-2.19,-8.81
  other v1: -18.669,-8.614 -18.669,-8.014 -18.669,-7.414
  other v2: -2.05,-8.764 -1.491,-8.764
VXO: 
XGND: 
pads on no net: T1.1 T1.2 T1.7 T1.8

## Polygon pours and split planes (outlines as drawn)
SGND on Bottom Layer "Bottom Layer-No Net" (solid, remove dead copper, pour order 80): -0.879,-3.418 -0.597,-3.418 -0.402,-3.222 -0.402,-2.701 -0.402,-0.328 -0.567,-0.162 -5.915,-0.162 -6.11,-0.357 -6.11,-1.767 -6.014,-1.863 -4.983,-1.863 -4.777,-1.656 -4.728,-1.607 -3.873,-1.607 -2.308,-1.607 -1.59,-2.325 -1.109,-2.806 -1.109,-3.02 -1.109,-3.273 -0.984,-3.397
PGND on Bottom Layer "Bottom Layer-No Net" (solid, remove dead copper, pour order 74): -21.67,-24.931 -21.67,-21.606 -20.291,-20.227 -18.556,-18.492 -17.05,-18.492 -5.791,-18.492 -5.412,-18.871 -5.412,-19.956 -5.571,-20.116 -7.061,-20.116 -7.346,-20.4 -7.346,-28.35 -7.346,-28.895 -7.578,-29.127 -8.072,-29.621 -8.805,-29.621 -16.742,-29.621 -18.088,-28.275 -19.769,-26.594 -20.846,-26.594 -21.653,-25.787 -21.653,-25.003
PGND on Bottom Layer "Bottom Layer-No Net" (solid, remove dead copper, pour order 71): -3.175,-29.331 -1.752,-29.331 -1.354,-28.932 -1.354,-20.155 -0.63,-19.431 -1.108,-18.952 -1.823,-18.952 -2.668,-18.952 -3.112,-19.397 -3.146,-19.43 -3.407,-19.691 -3.407,-28.623 -3.407,-28.925 -3.407,-29.216 -3.291,-29.332
PGND on Bottom Layer "Bottom Layer-No Net" (solid, remove dead copper, pour order 104): -23.237,-19.614 -23.237,-33.44 -20.206,-36.47 -20.206,-38.288 -20.624,-38.706 -23.062,-38.706 -26.145,-35.623 -28.051,-35.623 -29.958,-33.716 -29.958,-30.638 -27.004,-27.684 -27.004,-21.174 -25.381,-19.551 -23.386,-19.551
PGND on Bottom Layer "Bottom Layer-No Net" (solid, remove dead copper, pour order 81): -37.216,-32.792 -34.307,-32.792 -33.686,-33.413 -33.686,-34.994 -33.433,-35.247 -31.038,-35.247 -30.737,-34.946 -30.737,-31.53 -31.187,-31.08 -37.177,-31.08 -37.218,-31.121
HV on Bottom Layer "Bottom Layer-No Net" (solid, remove dead copper, pour order 97): -19.613,-30.257 -26.011,-30.257 -26.513,-30.759 -26.513,-32.833 -25.924,-33.423 -23.254,-33.423 -20.206,-36.47 -20.206,-40.63 -19.837,-41 -15.846,-41 -15.653,-40.806 -15.653,-36.564 -13.573,-34.483 -13.573,-33.015 -13.837,-32.751 -15.091,-32.751 -16.325,-33.985 -18.427,-33.985 -19.316,-33.095 -19.316,-30.554
SGND on Bottom Layer "Bottom Layer-No Net" (solid, remove dead copper, pour order 112): -17.63,-6.933 -18.129,-6.434 -18.368,-6.434 -25.739,-6.434 -25.937,-6.236 -25.937,-1.514 -25.007,-0.584 -10.042,-0.584 -9.621,-1.005 -9.621,-4.325 -10.205,-4.909 -10.34,-5.043 -11.553,-5.043 -14.287,-5.043 -16.12,-6.876 -16.12,-9.405 -17.63,-9.405
SGND on Top Layer "Bottom Layer-No Net" (solid, remove dead copper, pour order 78): 2.338,-4.47 -13.574,-4.47 -15.485,-6.382 -16.12,-7.017 -16.12,-9.405 -17.63,-9.405 -17.63,-7.121 -17.984,-6.767 -30.729,-6.767 -31.163,-6.333 -31.163,-1.66 -31.012,-1.509 -30.802,-1.3 -29.7,-1.3 -29.7,0 -0.73,0 -0.429,-0.3 -0.402,-0.328 -0.402,-0.634 -0.402,-2.701 -0.151,-2.952 2.338,-2.952
VIN on Top Layer "Bottom Layer-No Net" (solid, remove dead copper, pour order 73): -13.16,-4.057 -15.485,-6.382 -15.485,-8.104 -15.485,-9.371 -15.427,-9.429 -15.236,-9.62 -13.524,-9.62 -1.385,-9.62 -1.207,-9.443 -1.148,-9.383 -1.148,-7.298 -1.148,-7.131 -0.684,-6.668 -0.596,-6.58 2.338,-6.58 2.338,-5.073 -0.022,-5.073 -0.1,-4.994 -0.335,-4.759 -0.676,-4.759 -2.371,-4.759 -3.074,-4.057 -13.16,-4.057
PGND on Top Layer "Bottom Layer-No Net" (solid, remove dead copper, pour order 82): -30.885,-32.045 -30.885,-30.814 -21.863,-21.792 -21.856,-21.792 -17.96,-17.896 -17.96,-17.028 -18.891,-16.097 -25.25,-16.097 -29.659,-20.506 -29.659,-25.214 -33.567,-29.123 -33.567,-32.774 -33.249,-33.092 -31.202,-33.092 -30.886,-32.777
PGND on Top Layer "Bottom Layer-No Net" (solid, remove dead copper, pour order 100): -23.142,-39.312 -21.269,-41.185 -2.634,-41.185 -2.281,-40.832 -2.281,-16.863 -2.409,-16.735 -13.548,-16.735 -16.675,-16.735 -17.389,-17.449 -17.497,-17.557 -17.497,-17.744 -17.497,-20.744 -17.497,-20.818 -17.858,-21.178 -17.91,-21.23 -18.693,-21.23 -19.677,-21.23 -20.246,-21.799 -22.502,-24.055 -22.502,-24.547 -22.502,-30.634 -21.101,-32.036 -21.101,-33.57 -21.388,-33.857 -23.747,-36.216 -23.747,-37.903 -23.747,-38.708 -23.142,-39.312
PGND on Top Layer "Bottom Layer-No Net" (solid, remove dead copper, pour order 95): -25.912,-26.179 -25.912,-26.222 -27.805,-28.115 -30.232,-30.542 -30.232,-31.377 -30.232,-34.3 -30.232,-36.526 -29.727,-37.031 -29.186,-37.573 -26.96,-37.573 -24.882,-37.573 -23.142,-39.312 -22.556,-38.727 -21.657,-38.727 -21.657,-32.247 -22.882,-31.022 -22.882,-30.667 -22.882,-23.782
PGND on Top Layer "Bottom Layer-No Net" (solid, remove dead copper, pour order 93): -17.96,-17.896 -17.96,-20.547 -18.251,-20.838 -19.797,-20.838 -21.355,-22.396 -24.317,-25.358 -24.565,-25.358 -24.565,-20.791 -24.435,-20.661 -20.494,-16.719 -19.207,-16.719 -18.268,-16.719 -17.96,-17.028 -17.96,-17.641
PGND on Top Layer "Bottom Layer-No Net" (solid, remove dead copper, pour order 88): -27.108,-24.983 -25.912,-26.179 -25.912,-26.984 -25.912,-31.13 -26.658,-31.876 -27.564,-31.876 -28.404,-32.715 -28.404,-36.129 -26.96,-37.573 -24.882,-37.573 -24.07,-38.384 -23.142,-39.312 -22.456,-39.312 -22.242,-39.312 -21.657,-38.727 -21.657,-32.93 -21.657,-32.247 -22.549,-31.354 -22.882,-31.022 -22.882,-29.627 -22.882,-28.451 -22.882,-22.741 -23.862,-21.76 -23.957,-21.665 -25.934,-21.665 -27.169,-22.901 -27.169,-24.421
SGND on Signal Layer 1 "Bottom Layer-No Net" (solid, remove dead copper, pour order 85): -11.284,-7.361 -11.077,-7.568 -9.712,-7.568 -9.495,-7.351 -9.495,-6.158 -8.78,-5.444 -2.899,-5.444 -1.926,-4.47 2.338,-4.47 2.338,-2.952 -0.151,-2.952 -0.402,-2.701 -0.402,-0.634 -0.761,-0.274 -16.266,-0.274 -17.63,-1.638 -17.63,-9.405 -16.12,-9.405 -16.12,-6.65 -13.268,-3.798 -4.121,-3.798 -3.478,-4.441 -9.668,-4.441 -11.284,-6.056
VIN on Signal Layer 1 "Bottom Layer-No Net" (solid, remove dead copper, pour order 91): -13.16,-4.057 -15.485,-6.382 -15.485,-9.606 -1.921,-9.606 -1.353,-9.037 -1.353,-7.336 -0.159,-6.143 -0.159,-5.31 -0.164,-5.286 -1.394,-4.057
PGND on Signal Layer 1 "Bottom Layer-No Net" (solid, remove dead copper, pour order 101): -27.033,-22.533 -27.033,-23.356 -28.691,-25.014 -30.232,-26.556 -30.549,-26.872 -30.549,-31.129 -30.549,-36.209 -29.186,-37.573 -24.882,-37.573 -21.269,-41.185 -21.269,-34.553 -20.844,-34.128 -20.883,-34.089 -20.883,-32.795 -20.883,-30.577 -24.794,-26.666 -24.446,-26.318 -24.446,-23.14 -24.446,-22.485 -24.904,-22.026 -26.526,-22.026 -27.033,-22.533
PGND on Signal Layer 1 "Bottom Layer-No Net" (solid, remove dead copper, pour order 99): -23.142,-39.312 -21.269,-41.185 -2.634,-41.185 -2.281,-40.832 -2.281,-16.863 -2.409,-16.735 -13.548,-16.735 -16.675,-16.735 -17.389,-17.449 -17.497,-17.557 -17.497,-17.744 -17.497,-20.744 -17.497,-20.818 -17.858,-21.178 -17.91,-21.23 -18.693,-21.23 -19.677,-21.23 -20.246,-21.799 -22.502,-24.055 -22.502,-24.547 -22.502,-30.634 -21.101,-32.036 -21.101,-33.57 -21.388,-33.857 -23.747,-36.216 -23.747,-37.903 -23.747,-38.708 -23.142,-39.312
NetBD1_3 on Signal Layer 1 "Bottom Layer-No Net" (solid, remove dead copper, pour order 92): -22.349,-16.256 -24.232,-16.256 -24.794,-16.818 -24.794,-26.666 -22.671,-28.789 -22.263,-29.197 -22.187,-29.273 -19.931,-29.273 -19.644,-29.273 -19.298,-28.927 -19.298,-27.136 -20.033,-26.401 -21.567,-24.867 -21.567,-24.45 -21.567,-16.924 -22.155,-16.336
SGND on Signal Layer 2 "Bottom Layer-No Net" (solid, remove dead copper, pour order 94): 2.338,-2.952 -0.151,-2.952 -1.149,-1.954 -4.855,-1.954 -6.184,-0.625 -27.986,-0.625 -30.109,-2.748 -30.109,-9.429 -29.366,-10.172 -28.199,-10.172 -27.735,-9.709 -27.735,-4.39 -26.103,-2.758 -8.852,-2.758 -7.14,-4.47 2.308,-4.47 2.338,-4.441
PGND on Signal Layer 2 "Bottom Layer-No Net" (solid, remove dead copper, pour order 102): -20.979,-38.214 -20.979,-30.481 -24.794,-26.666 -24.794,-23.948 -24.517,-23.671 -24.517,-22.443 -24.565,-22.396 -25.108,-21.853 -25.805,-21.853 -26.275,-21.853 -27.026,-22.605 -27.074,-22.605 -29.659,-25.189 -30.549,-26.08 -30.549,-26.872 -30.549,-36.209 -29.186,-37.573 -24.882,-37.573 -23.942,-38.512
PGND on Signal Layer 2 "Bottom Layer-No Net" (solid, remove dead copper, pour order 98): -23.142,-39.312 -21.269,-41.185 -2.634,-41.185 -2.281,-40.832 -2.281,-16.863 -2.409,-16.735 -13.548,-16.735 -16.675,-16.735 -17.389,-17.449 -17.497,-17.557 -17.497,-17.744 -17.497,-20.744 -17.497,-20.818 -17.858,-21.178 -17.91,-21.23 -18.693,-21.23 -19.677,-21.23 -20.246,-21.799 -22.502,-24.055 -22.502,-24.547 -22.502,-30.634 -21.101,-32.036 -21.101,-33.57 -21.388,-33.857 -23.747,-36.216 -23.747,-37.903 -23.747,-38.708 -23.142,-39.312
NetBD1_3 on Signal Layer 2 "Bottom Layer-No Net" (solid, remove dead copper, pour order 89): -22.349,-16.256 -24.232,-16.256 -24.794,-16.818 -24.794,-26.666 -22.671,-28.789 -22.263,-29.197 -22.187,-29.273 -19.931,-29.273 -19.644,-29.273 -19.298,-28.927 -19.298,-27.136 -20.033,-26.401 -21.567,-24.867 -21.567,-24.45 -21.567,-16.924 -22.155,-16.336

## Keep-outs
Keep-Out Layer:
  lines w0.1: -13.819,-10.764 -26.919,-10.764 -26.919,-9.664 -13.819,-9.664 ; -13.719,-10.764 -13.719,-9.664 ; -39.709,-40.7 -29.709,-40.702 -29.71,-42.002 0,-42.002 0,-37.5 2.5,-37.5 2.5,-32.5 0,-32.5 0,-9.269 2.5,-9.269 2.5,-2.769 0,-2.769 0,0 -29.7,0 -29.7,-1.3 -31.7,-1.3 -31.7,-26.8 -39.7,-26.8 -39.709,-40.7 ; -38.3,-38.3 -37.2,-38.3 -37.2,-36.9 -38.3,-36.9 -38.3,-38.3 ; -38.3,-35.7 -37.2,-35.7 -37.2,-34.3 -38.3,-34.3 -38.3,-35.7 ; -38.3,-33 -37.2,-33 -37.2,-27.7 -38.3,-27.7 -38.3,-33 ; -27.6,-12.862 -13,-12.862 -13,-11.862 -27.6,-11.862 -27.6,-12.862

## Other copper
Top Layer:
  region net VOUT1: -18.808,-7.128 -18.52,-7.128 -18.356,-7.292 -18.356,-8.746 -18.5,-8.89 -18.854,-8.89 -18.964,-8.781 -18.964,-7.284
  region net VOUT1: -2.215,-8.525 -1.374,-8.525 -1.212,-8.364 0.075,-8.364 0.393,-8.046 0.393,-7.417 0.647,-7.163 2.45,-7.163 2.455,-7.169 2.455,-8.364 2.458,-8.366 2.458,-8.807 2.273,-8.992 -0.166,-8.992 -0.515,-8.643 -1.022,-8.643 -1.425,-9.046 -2.183,-9.046 -2.302,-8.927 -2.302,-8.612
  region net NetBD1_3: -37.168,-29.596 -35.239,-29.596 -35.012,-29.369 -35.012,-28.218 -35.249,-27.981 -37.168,-27.981
  region net PGND: -37.065,-32.792 -33.55,-32.792 -33.249,-33.092 -33.249,-31.132 -33.567,-30.814 -33.834,-31.08 -37.065,-31.08
  region net SGND: -29.751,-8.445 -28.046,-8.445 -27.735,-8.756 -27.735,-9.709 -28.199,-10.172 -29.366,-10.172 -30.109,-9.429 -30.109,-8.672 -29.942,-8.505
  region net SGND: -11.12,-6.424 -9.688,-6.424 -9.513,-6.598 -9.513,-7.43 -9.686,-7.603 -11.093,-7.603 -11.302,-7.394 -11.302,-6.605
  region net NetBD1_1: -24.922,-41.077 -24.922,-40.009 -25.782,-39.15 -30.673,-39.15 -35.342,-34.481 -37.171,-34.481 -37.191,-34.501 -37.191,-35.477 -37.171,-35.497 -35.626,-35.497 -29.87,-41.253 -25.098,-41.253
  pour cut-out: -4.522,-31.444 -4.522,-34.43 -3.922,-35.03 -2.412,-35.03 -1.935,-34.553 -1.935,-32.301 -2.792,-31.444
  region net NewNet33: -26.308,-7.128 -26.02,-7.128 -25.856,-7.292 -25.856,-8.746 -26,-8.89 -26.354,-8.89 -26.464,-8.781 -26.464,-7.284
  region net SCL: -24.808,-7.128 -24.52,-7.128 -24.356,-7.292 -24.356,-8.746 -24.5,-8.89 -24.854,-8.89 -24.964,-8.781 -24.964,-7.284
  region net SDA: -23.308,-7.128 -23.02,-7.128 -22.856,-7.292 -22.856,-8.746 -23,-8.89 -23.354,-8.89 -23.464,-8.781 -23.464,-7.284
  region net SWCLK: -21.808,-7.128 -21.52,-7.128 -21.356,-7.292 -21.356,-8.746 -21.5,-8.89 -21.854,-8.89 -21.964,-8.781 -21.964,-7.284
  region net SWDIO: -20.308,-7.128 -20.02,-7.128 -19.856,-7.292 -19.856,-8.746 -20,-8.89 -20.354,-8.89 -20.464,-8.781 -20.464,-7.284
  region net VOUT1: -18.964,-8.781 -18.964,-6.238 -18.686,-5.961 -18.356,-6.291 -18.356,-8.746 -18.5,-8.89 -18.854,-8.89
  pour cut-out: -1.303,-27.787 ccw(c-3.305,-27.787) -3.305,-25.785 -3.306,-25.785 ccw(c-3.306,-27.778) -5.299,-27.778 ccw(c-3.29,-27.778) -3.29,-29.787 ccw(c-3.29,-27.8) -1.303,-27.8
  pour cut-out: -17.273,-29.422 ccw(c-19.813,-29.422) -19.813,-26.882 -20.335,-26.882 ccw(c-20.335,-29.422) -22.875,-29.422 -22.875,-29.938 ccw(c-20.335,-29.938) -20.335,-32.478 -19.813,-32.478 ccw(c-19.813,-29.938) -17.273,-29.938
Signal Layer 1:
  pour cut-out: -24.77,-29.592 -24.068,-28.89 -23.583,-28.89 -23.583,-29.182 -24.445,-30.045
Signal Layer 2:
  region net VIN: -1.592,-5.046 -0.656,-5.046 -0.292,-5.409 -0.292,-5.78 -0.69,-6.177 -1.24,-6.177 -1.755,-5.662 -1.755,-5.208
  region net VOUT1: -19.242,-6.226 -19.242,-5.966 -19.069,-5.793 -14.211,-5.793 -11.549,-8.454 -1.44,-8.454 -1.235,-8.659 -1.235,-8.856 -1.425,-9.046 -11.731,-9.046 -14.364,-6.413 -19.055,-6.413
  region net SGND: -4.95,-0.283 -0.752,-0.283 -0.402,-0.634 -0.402,-2.833 -0.553,-2.984 -1.362,-2.984 -1.892,-2.454 -1.892,-1.99 -2.243,-1.639 -4.769,-1.639 -5.14,-1.267 -5.14,-0.473
  pour cut-out: -24.77,-29.592 -24.068,-28.89 -23.583,-28.89 -23.583,-29.182 -24.445,-30.045
  pour cut-out: -4.491,-30.101 -3.934,-29.545 -1.603,-29.545 -0.813,-30.335 -0.813,-40.701 -1.556,-41.444 -21.444,-41.444 -23.942,-38.946 -23.942,-38.512 -21.784,-38.512 -21.657,-38.384 -21.149,-38.384 -20.071,-39.462 -4.065,-39.462 -3.035,-38.433 -3.035,-35.274 -2.174,-34.413 -2.174,-32.434 -2.503,-32.106 -3.859,-32.106 -4.491,-31.475
  region net PGND: -21.269,-41.185 -23.942,-38.512 -23.942,-36.607 -23.503,-36.167 -22.016,-36.167 -21.657,-36.526 -21.657,-38.356 -20.218,-39.795 -3.973,-39.795 -3.18,-39.001 -2.598,-39.001 -2.376,-39.224 -2.376,-40.587 -2.973,-41.185
  region net PGND: -3.799,-29.78 -1.698,-29.78 -1.055,-30.423 -1.055,-40.511 -1.736,-41.192 -3.695,-41.192 -3.81,-41.077 -3.81,-39.631 -2.761,-38.582 -2.761,-35.379 -1.935,-34.553 -1.935,-32.301 -2.388,-31.848 -3.751,-31.848 -4.238,-31.362 -4.238,-30.219
  region net SCL: -25.12,-9.616 -25.12,-6.79 -24.728,-6.398 -24.626,-6.398 -24.216,-6.807 -24.216,-9.616
  region net SDA: -23.62,-9.616 -23.62,-6.79 -23.228,-6.398 -23.126,-6.398 -22.716,-6.807 -22.716,-9.616
  region net SWCLK: -22.12,-9.616 -22.12,-6.79 -21.728,-6.398 -21.626,-6.398 -21.216,-6.807 -21.216,-9.616
  region net SWDIO: -20.62,-9.616 -20.62,-6.79 -20.228,-6.398 -20.126,-6.398 -19.716,-6.807 -19.716,-9.616
  region net VOUT1: -19.12,-9.616 -19.12,-6.263 -18.216,-6.263 -18.216,-9.616
Bottom Layer:
  region net VIN: -15.293,-7.177 -13.551,-7.177 -13.272,-7.457 -13.272,-9.111 -13.764,-9.603 -15.485,-9.603 -15.485,-7.37
  region net VIN: -0.694,-6.231 -0.204,-5.742 -0.204,-5.403 -1.174,-4.433 -1.56,-4.433 -1.748,-4.621 -1.748,-5.669 -1.185,-6.231
  region net OPTO: -3.034,-4.926 -2.255,-4.926 -2.093,-5.087 -2.093,-5.928 -1.564,-6.458 -1.564,-7.797 -1.696,-7.93 -3.048,-7.93 -3.171,-7.807 -3.171,-5.063
  region net VOUT1: -19.125,-9.608 -19.125,-6.468 -19.215,-6.377 -19.215,-5.995 -19.07,-5.85 -18.23,-5.85 -18.086,-5.994 -18.086,-6.442 -18.223,-6.58 -18.223,-9.608
  region net NetC21_1: -5.079,-7.949 -3.865,-7.949 -3.696,-7.78 -3.696,-4.736 -3.452,-4.492 -2.328,-4.492 -2.211,-4.375 -2.211,-3.786 -2.432,-3.565 -4.558,-3.565 -4.673,-3.68 -4.673,-5.868 -5.246,-6.441 -5.246,-7.782
  region net VIN: -6.001,-2.26 -4.817,-2.26 -4.511,-1.954 -2.392,-1.954 -1.437,-2.909 -1.437,-4.17 -1.174,-4.433 -1.174,-5.987 -1.302,-6.115 -1.748,-5.669 -1.748,-4.621 -1.933,-4.436 -1.933,-3.471 -2.195,-3.209 -5.948,-3.209 -6.11,-3.047 -6.11,-2.369
  region net SGND: -17.63,-9.405 -17.63,-6.933 -17.323,-6.626 -16.358,-6.626 -16.114,-6.87 -16.12,-6.876 -16.12,-9.405
  region net PGND: -3.013,-22.074 -2.424,-22.074 -2.291,-21.94 -2.291,-20.039 -1.683,-19.431 -0.63,-19.431 -0.372,-19.173 -0.372,-18.201 -1.209,-17.364 -1.209,-15.877 -1.351,-15.735 -2.552,-15.735 -2.7,-15.883 -2.7,-18.967 -3.079,-19.345 -3.079,-19.363 -3.146,-19.43 -3.146,-21.941
  region net NetD4_K: -4.998,-15.737 -3.818,-15.737 -3.417,-16.139 -3.417,-18.983 -3.77,-19.337 -4.805,-19.337 -5.023,-19.118 -5.023,-15.762
  region net SGND: -11.749,-3.212 -10.294,-3.212 -10.071,-3.436 -10.071,-4.774 -10.34,-5.043 -11.553,-5.043 -11.932,-4.664 -11.932,-3.396
  region net SGND: -7.424,-6.395 -12.587,-6.395 -12.827,-6.636 -12.827,-7.821 -12.582,-8.067 -10.511,-8.067 -9.895,-8.683 -6.96,-8.683 -6.555,-8.278 -6.555,-7.265
  region net A: -6.051,-3.593 -5.241,-3.593 -5.103,-3.732 -5.103,-5.608 -5.395,-5.901 -5.985,-5.901 -6.139,-5.747 -6.139,-3.681
  region net OPTO: -6.994,-4.927 -6.831,-5.09 -6.831,-5.751 -7.032,-5.952 -9.973,-5.952 -10.067,-5.858 -10.067,-5.601 -9.393,-4.927
  region net NetBD1_1: -27.336,-37.084 -26.116,-37.084 -25.782,-37.418 -25.782,-39.15 -24.922,-40.009 -24.922,-41.077 -25.098,-41.253 -27.283,-41.253 -27.471,-41.066 -27.471,-37.218
  region net NetBD1_1: -37.171,-34.481 -35.342,-34.481 -35.157,-34.666 -35.157,-35.291 -35.363,-35.497 -37.181,-35.497
  region net NetN_1: -37.174,-37.099 -34.003,-37.099 -33.813,-37.288 -33.813,-40.773 -33.968,-40.928 -36.799,-40.928 -37.187,-40.54 -37.187,-37.113 -37.175,-37.101
  region net PGND: -7.176,-29.441 -5.529,-29.441 -5.362,-29.608 -5.362,-32.005 -5.677,-32.32 -7.248,-32.32 -7.392,-32.175 -7.392,-29.658
  region net PGND: -6.429,-17.974 -18.256,-17.974 -18.516,-18.235 -19.881,-18.235 -20.33,-17.785 -20.33,-16.642 -19.785,-16.097 -15.213,-16.097 -14.434,-16.876 -10.567,-16.876 -9.832,-16.141 -6.359,-16.141 -6.081,-16.419 -6.081,-17.627
  region net NetR15_1: -23.597,-25.962 -22.277,-25.962 -22.097,-26.142 -22.097,-28.694 -22.293,-28.89 -23.583,-28.89 -23.774,-28.698 -23.774,-26.138
  region net SGND: -31.249,-9.742 -29.313,-9.742 -28.882,-10.172 -28.199,-10.172 -27.65,-9.623 -27.65,-8.501 -28.302,-7.849 -31.174,-7.849 -31.412,-8.088 -31.412,-9.579
  region net NetRX3_2: -32.058,-37.069 -29.253,-37.069 -29.047,-37.275 -29.047,-40.792 -29.271,-41.015 -32.033,-41.015 -32.243,-40.805 -32.243,-37.255
  region net NewNet33: -26.62,-9.616 -26.62,-7.158 -26.17,-6.707 -25.716,-7.161 -25.716,-9.616
  region net SCL: -25.12,-9.616 -25.12,-7.158 -24.963,-7 -24.377,-7 -24.216,-7.161 -24.216,-9.616
  region net SDA: -23.62,-9.616 -23.62,-7.158 -23.463,-7 -22.877,-7 -22.716,-7.161 -22.716,-9.616
  region net SWCLK: -22.12,-9.616 -22.12,-7.158 -21.963,-7 -21.377,-7 -21.216,-7.161 -21.216,-9.616
  region net SCL: 2.409,-3.361 -0.003,-3.361 -0.45,-3.808 -0.45,-4.725 -0.404,-4.771 0.088,-4.771 0.489,-4.371 2.409,-4.371
  region net SDA: 2.388,-4.968 0.406,-4.968 0.118,-5.256 0.118,-6.222 0.205,-6.309 0.548,-5.965 2.388,-5.965
  region net SWCLK: 2.394,-6.57 0.588,-6.57 0.042,-7.116 0.042,-7.473 0.138,-7.569 2.394,-7.569
  region net SWDIO: 2.401,-9.165 0.445,-9.165 0.134,-8.854 0.134,-8.813 -0.182,-8.813 -0.326,-8.669 0.173,-8.17 2.401,-8.17
  region net SWDIO: -20.62,-9.616 -20.62,-7.158 -20.463,-7 -19.877,-7 -19.716,-7.161 -19.716,-9.616
  region net NewNet33: -9.332,-4.259 -9.068,-4.523 -6.968,-4.523 -6.837,-4.392 -6.837,-0.703 -7.273,-0.268 -8.57,-0.268 -8.73,-0.429 -9.76,-0.429 -9.832,-0.5 -9.332,-1
  region net ISET: -6.914,-24.404 -6.914,-26.488 -6.384,-27.018 -4.095,-27.018 -3.982,-26.905 -3.982,-26.248 -4.075,-26.155 -5.019,-26.155 -5.26,-25.914 -5.26,-24.648 -5.503,-24.404
  region net M: -7.572,-33.708 -7.572,-33.04 cw(c-7.383,-33.04) -7.383,-32.851 -5.794,-32.851 ccw(c-5.794,-32.189) -5.326,-32.657 -4.771,-32.103 cw(c-4.618,-32.256) -4.618,-32.039 -4.617,-32.039 cw(c-4.617,-32.302) -4.354,-32.302 -4.354,-32.31 cw(c-4.583,-32.31) -4.421,-32.472 -5.596,-33.646 cw(c-6.101,-33.141) -6.101,-33.855 -7.424,-33.855 cw(c-7.424,-33.708)
  region net NetC6_1: -23.229,-24.366 -22.429,-24.366 ccw(c-22.429,-23.825) -22.046,-24.207 -21.957,-24.118 cw(c-20.161,-25.914) -20.161,-23.374 -19.387,-23.374 ccw(c-19.387,-22.77) -18.783,-22.77 -18.783,-22.614 ccw(c-19.342,-22.614) -19.342,-22.055 -21.863,-22.055 ccw(c-21.863,-24.244) -23.411,-22.696 -23.503,-22.788 ccw(c-22.86,-23.431) -23.769,-23.431 -23.769,-24.061 ccw(c-23.464,-24.061) -23.464,-24.367
  region net PGND: -3.636,-41.188 -2.367,-41.188 ccw(c-2.367,-41.005) -2.183,-41.005 -2.183,-39.663 ccw(c-2.322,-39.663) -2.322,-39.524 -3.621,-39.524 ccw(c-3.621,-39.71) -3.806,-39.71 -3.806,-41.015 ccw(c-3.636,-41.015) -3.636,-41.185
  region net NetC6_1: -7.408,-41.144 -4.757,-41.144 ccw(c-4.757,-40.74) -4.353,-40.74 -4.353,-38.407 ccw(c-4.584,-38.407) -4.584,-38.176 -7.326,-38.176 ccw(c-7.326,-38.571) -7.721,-38.571 -7.721,-40.848 ccw(c-7.425,-40.848) -7.425,-41.144
  region net Bais-L: -7.377,-34.913 -4.76,-34.913 cw(c-4.76,-35.145) -4.528,-35.145 -4.528,-37.594 cw(c-4.749,-37.594) -4.749,-37.815 -7.168,-37.815 cw(c-7.168,-37.261) -7.722,-37.261 -7.722,-35.101 cw(c-7.534,-35.101) -7.534,-34.913
  region net NetC4_1: -3.75,-36.821 -3.146,-36.821 cw(c-3.146,-37.039) -2.929,-37.039 -2.929,-38.792 cw(c-3.219,-38.792) -3.219,-39.082 -3.782,-39.082 cw(c-3.782,-38.903) -3.961,-38.903 -3.961,-37.007 cw(c-3.775,-37.007) -3.775,-36.821
  region net NetC4_2: -3.471,-32.857 -2.694,-32.857 cw(c-2.694,-33.16) -2.391,-33.16 -2.391,-36.04 cw(c-2.624,-36.04) -2.624,-36.273 -3.367,-36.273 cw(c-3.367,-35.972) -3.668,-35.972 -3.668,-35.427 ccw(c-4.963,-35.427) -4.047,-34.511 cw(c-3.488,-33.952) -4.279,-33.952 -4.279,-33.16 cw(c-3.977,-33.16) -3.977,-32.857
  region net NetC2_2: -11.9,-34.199 -10.907,-34.199 cw(c-10.907,-35.763) -9.343,-35.763 -9.343,-37.083 cw(c-9.678,-37.083) -9.678,-37.418 -11.625,-37.418 cw(c-11.625,-37.13) -11.913,-37.13 -11.913,-36.405 ccw(c-13.069,-36.405) -12.251,-35.588 -12.498,-35.342 cw(c-12.336,-35.18) -12.564,-35.18 -12.564,-34.52 cw(c-12.243,-34.52) -12.243,-34.198
  region net NetC1_2: -13.859,-40.996 cw(c-13.859,-40.466) -14.388,-40.466 -14.388,-36.774 cw(c-14.076,-36.774) -14.297,-36.553 -13.979,-36.235 cw(c-13.684,-36.53) -13.684,-36.113 -13.177,-36.113 cw(c-13.177,-36.449) -12.84,-36.449 -12.84,-38.037 ccw(c-12.137,-38.037) -12.137,-38.74 -10.085,-38.74 cw(c-10.085,-39.418) -9.407,-39.418 -9.407,-40.599 cw(c-9.801,-40.599) -9.801,-40.994
  region net NetL2_1: -17.864,-30.221 -16.708,-30.221 ccw(c-16.708,-29.934) -16.421,-29.934 cw(c-15.48,-29.934) -15.48,-28.993 -15.382,-28.993 ccw(c-15.382,-28.676) -15.066,-28.676 -15.066,-25.69 ccw(c-15.521,-25.69) -15.521,-25.235 -16.422,-25.235 ccw(c-16.422,-25.598) -16.679,-25.341 -17.404,-26.066 ccw(c-15.608,-27.862) -18.148,-27.862 -18.148,-29.941 ccw(c-17.87,-29.941) -17.87,-30.219
  region net SW: -14.784,-29.734 -9.438,-29.734 cw(c-9.438,-30.233) -8.939,-30.233 -8.939,-31.478 cw(c-9.254,-31.478) -9.254,-31.792 -15.143,-31.792 ccw(c-15.143,-32.469) -15.621,-31.991 -16.665,-33.035 cw(c-16.757,-32.943) -16.757,-33.073 -17.94,-33.073 cw(c-17.94,-32.862) -18.151,-32.862 -18.151,-32.018 cw(c-17.878,-32.018) -17.878,-31.745 ccw(c-17.878,-29.35) -16.185,-31.044 -15.699,-30.558 ccw(c-16.109,-30.148) -15.529,-30.148 cw(c-15.114,-30.148) -15.114,-29.733 -14.799,-29.733
  region net NetBD1_3: -37.168,-29.596 -31.487,-29.596 ccw(c-31.487,-27.056) -29.691,-28.852 -28.871,-28.031 ccw(c-30.667,-26.235) -28.127,-26.235 -28.127,-23.297 cw(c-25.587,-23.297) -27.383,-21.501 -26.413,-20.531 cw(c-24.617,-22.327) -24.617,-19.787 -22.87,-19.787 ccw(c-22.87,-18.676) -21.759,-18.676 -21.759,-17.033 ccw(c-22.557,-17.033) -22.557,-16.236 -24.196,-16.236 ccw(c-24.196,-18.776) -25.992,-16.979 -29.055,-20.042 ccw(c-27.259,-21.838) -29.799,-21.838 -29.799,-22.115 cw(c-29.973,-22.115) -29.973,-22.288 cw(c-29.973,-22.102) -30.159,-22.102 -30.159,-20.981 cw(c-29.016,-20.981) -29.824,-20.172 -29.566,-19.914 ccw(c-30.314,-19.166) -29.256,-19.166 -29.256,-18.372 -29.381,-18.246 -31.083,-18.246 ccw(c-31.083,-18.68) -31.517,-18.68 -31.517,-22.524 ccw(c-30.846,-22.524) -30.846,-23.195 -30.19,-23.195 cw(c-30.19,-23.355) -30.03,-23.355 cw(c-30.185,-23.355) -30.185,-23.51 -31.079,-23.51 ccw(c-31.079,-23.92) -31.489,-23.92 -31.489,-26.708 cw(c-31.809,-26.708) -31.809,-27.028 -37.168,-27.028
Multi-Layer:
  pour cut-out: -3.745,-39.337 -3.329,-39.337 -3.083,-39.583 -3.083,-41.288 -3.213,-41.418 -3.819,-41.418 -4,-41.237 -4,-39.591
  pour cut-out: -4.522,-31.444 -4.522,-30.132 -3.934,-29.545 -2.65,-29.545 -1.993,-30.202 -1.993,-31.443 -2.636,-32.086 -3.879,-32.086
